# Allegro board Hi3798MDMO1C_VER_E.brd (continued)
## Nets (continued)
NF_CSN0_EMMC_CMD: R212.2 U1.N22 U19.9 U22.W5
NF_DQ0_EMMC_D0: R189.2 U1.R23 U19.29 U22.H3
NF_DQ1_EMMC_D1: R12.2 U1.R22 U19.30 U22.H4
NF_DQ2_EMMC_D2: R29.2 U1.R21 U19.31 U22.H5
NF_DQ3_EMMC_D3: R58.2 U1.T21 U19.32 U22.J2
NF_DQ4_EMMC_D4: R176.2 U1.T20 U19.41 U22.J3
NF_DQ5_EMMC_D5: R177.2 U1.U22 U19.42 U22.J4
NF_DQ6_EMMC_D6: R188.2 U1.U23 U19.43 U22.J5
NF_DQ7_EMMC_D7_BOOT_SEL0: R33.1 R202.2 U1.U21 U19.44 U22.J6
NF_RDY0_EMMC_RST: C115.1 R203.2 U1.M21 U19.7 U22.U5
NF_REN_EMMC_CLK: R68.1 U19.8 U22.W6
NF_WEN_EMMC_DET: R56.2 U1.P21 U19.18
NF_WP: R89.1 R215.2 U19.19
PWR_OFF/ON: R40.1 R41.1 U1.J23
RECOVERY: C38.2 R25.2 S1.2 U1.J22
RF0: C89.1 L1.2 U7.3
RF1: C56.1 L7.2 U2.7 U7.2
RFF0: C88.1 J9.1 L1.1
RFF1: C50.1 J8.1 L7.1
RX+_PHY0: R63.1 U1.D5 U8.3 U8.6
RX-_PHY0: R64.1 U1.C5 U8.4 U8.5
SPDIF_OUT_BOOT_SEL1: R39.1 U1.A20
STANDBY_PWROFF: R5.1 R47.1 R73.1 R88.1 R98.1 U1.AB23
TX+_PHY0: R59.1 U1.B4 U8.1 U8.8
TX-_PHY0: R62.1 U1.A4 U8.2 U8.7
UART0_RXD: J18.2 R136.1 U1.AA22
UART0_TXD: J18.3 R135.2 U1.AA23
USB0_DM: C48.1 D5.1 J12.2 U1.A6
USB0_DP: C42.1 D4.1 J12.3 U1.B6
USB01_1V1: C334.1 C336.1 LB31.2 U1.G11
USB01_3V3: C10.1 C182.1 LB20.2 U1.D7
USB1_DM: J2.4 U1.B7 U2.4 U7.7
USB1_DP: J2.3 U1.C7 U2.2 U7.6
USB3_DM: J28.2 U1.AC18
USB3_DP: J28.3 U1.AB18
USB3_RXN: J28.5 U1.AB20
USB3_RXP: J28.6 U1.AC20
USB3_TXN: C62.2 U1.AA19
USB3_TXP: C70.2 U1.Y19
USB03_VBUS: C60.1 C265.1 C372.1 J12.1 J28.1 LB2.1 U26.5
USB_BOOT: R42.2 U1.H21
VDAC_3V3: C9.1 C85.1 LB14.2 U1.E20 U1.F19 U1.G19
XIN: C364.1 R1.2 U1.W23 X2.1
XOUT: R1.1 R14.1 U1.W22
$4N588: C84.1 R10.1 R52.1 U15.5
$4N589: L4.1 U15.3
$4N593: C30.1 R6.2 R47.2 U15.1
$4N676: C43.1 C71.1 R7.2 R21.1
$4N677: C76.1 R53.1 R70.1 R99.2 U11.6
$4N679: L2.1 U11.3
$4N687: C8.1 R73.2 U11.1
$4N714: C82.1 R13.2 R101.1 R110.1 U13.6
$4N715: C45.1 C72.1 R23.1 R102.2
$4N716: R102.1 R110.2
$4N719: L3.1 U13.3
$4N724: C5.1 R5.2 U13.1
$4N894: R7.1 R70.2
$4N901: R100.1 R105.1 U14.5
$4N903: D2.1 R95.1 U14.1
$4N904: C83.2 R104.1
$4N905: C24.1 C83.1 U14.6
$4N906: R4.2 U14.7
$4N919: C44.1 U14.8
$4N923: C65.1 R95.2
$4N925: C65.2 L5.1 U14.3
$4N944: J1.1 J5.2 J10.1 R81.1
$5N541: Q4.3 R118.2 R144.2
$5N542: C6.2 Q13.1 Q14.1 R118.1
$5N549: Q4.1 R98.2
$6N188: C365.1 R14.2 X2.3
$6N1407: R173.1 U1.E6
$6N2001: R61.2 U1.Y17
$6N2177: R24.1 R85.1 U1.L19
$6N2378: R68.2 U1.N23
$7N1408: C250.2 U1.G17
$7N1639: R82.2 R87.2 U1.D8
$7N1763: R32.2 U1.F20
$7N1940: C34.1 R42.1 S2.1 S2.2
$8N1506: R45.1 U1.W16
$8N1694: R18.2 U1.AC8
$8N1695: R35.2 U1.AB8
$8N1696: R36.2 U1.AA7
$8N1697: R37.2 U1.AB7
$9N2352: C255.2 U1.T19
$11N1183: R46.2 U3.L8
$11N1256: C328.1 R11.2 R15.1
$12N1465: R71.2 U6.L8
$12N1636: C330.1 R16.2 R17.1
$13N604: C123.1 C124.1 U22.K2
$13N727: R57.1 U19.39
$13N772: R80.2 U19.38
$14N447: R220.1 U26.3
$14N448: R106.2 U26.4
$14N684: C70.1 J28.9
$14N685: C62.1 J28.8
$15N955: Q2.1 R31.2
$15N957: Q1.1 R22.2
$16N873: C363.1 R66.1 R90.2 R229.1 U5.5
$16N884: C32.1 U5.7
$16N889: C33.2 U5.6
$16N895: C32.2 U5.8
$16N998: R43.2 R44.1 R48.2
$16N1000: R43.1 U5.11
$16N1002: C351.2 R193.1
$16N1003: C55.1 R27.2 U5.2
$16N1006: C317.1 R19.1 R27.1 R193.2
$16N1021: C55.2 R19.2 R74.2 R146.1 U5.3
$16N1028: C54.2 R28.1 U5.13
$16N1029: C54.1 R20.1 R72.1 R145.1 U5.12
$16N1040: C350.1 R194.2
$16N1041: C316.1 R20.2 R28.2 R194.1
$17N163: C154.1 C297.1 T2.7
$17N165: J25.9 R67.1
$17N170: J25.11 R79.1
$17N171: J25.7 J25.8 R270.2
$17N172: R271.2 T2.15
$17N173: R269.2 T2.10
$17N175: J25.6 T2.9
$17N176: J25.3 T2.11
$17N177: C23.1 R269.1 R270.1 R271.1 R272.1
$17N178: J25.1 T2.16
$17N179: J25.2 T2.14
$17N180: J25.4 J25.5 R272.2
$17N184: C153.1 C307.1 T2.2
$17N255: R59.2 T2.1
$17N256: R62.2 T2.3
$17N257: R63.2 T2.6
$17N258: R64.2 T2.8
$19N506: D19.1 R268.1

Pads without a net: ID1 1; ID2 1; ID3 1; ID4 1; ID5 1; ID6 1; J2 1 6 8 11; J26 14; M20 1; M21 1; T2 4 5 12 13; U1 A8 A9 A11 A12 AA21 B9 B11 B12 C1 C2 C9 C10 C11 C12 D3 E1 E2 E3 F1 F2 F3 G5 G21 J21 K20 K21 L22 L23 Y22; U2 3; U3 J1 J9 L1 L9; U6 J1 J9 L1 L9; U7 4 9 10; U11 5; U13 5; U19 3 4 5 6 10 11 14 15 20 21 22 26 27 28 33 35 40 45 46 47; U22 A4 A6 A9 A11 AA1 AA2 AA7 AA8 AA9 AA10 AA11 AA12 AA13 AA14 AE1 AE14 AG2 AG13 AH4 AH6 AH9 AH11 B2 B13 D1 D14 H1 H2 H6 H7 H8 H9 H10 H11 H12 H13 H14 J1 J7 J8 J9 J10 J11 J12 J13 J14 K1 K3 K5 K7 K8 K9 K10 K11 K12 K13 K14 L1 L2 L3 L4 L12 L13 L14 M1 M2 M3 M5 M8 M9 M10 M12 M13 M14 N1 N2 N3 N10 N12 N13 N14 P1 P2 P3 P10 P12 P13 P14 R1 R2 R3 R5 R12 R13 R14 T1 T2 T3 T5 T12 T13 T14 U1 U2 U3 U6 U7 U10 U12 U13 U14 V1 V2 V3 V12 V13 V14 W1 W2 W3 W7 W8 W9 W10 W11 W12 W13 W14 Y1 Y3 Y6 Y7 Y8 Y9 Y10 Y11 Y12 Y13 Y14

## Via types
v1: diameter 0.508, hole 0.254, TOP to BOTTOM, 1411 vias
v2: diameter 0.457, hole 0.203, TOP to BOTTOM, 873 vias

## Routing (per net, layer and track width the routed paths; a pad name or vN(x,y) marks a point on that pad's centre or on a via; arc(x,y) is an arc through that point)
1V1_CORE: length 8.2
  TOP w0.381: 82.04,31.36 83.57,31.36 84.77,30.16 84.77,26.07 C82.2
  TOP w0.508: R101.2 C82.2
  vias: v1(76.45,33.01) v1(76.43,32.23) v1(76.41,31.53) v1(77.16,32.23) v1(77.13,31.52) v1(77.19,32.99) v1(77.98,32.99) v1(78.71,32.99) v2(65.22,46.63) v2(65.22,45.84) v2(65.22,45.03) v2(66.02,45.84) v2(66.02,45.03) v2(66.82,45.84) v2(67.62,48.25) v2(67.62,45.83) v2(68.42,48.23) v2(68.42,47.43) v2(68.42,45.83) v2(70.66,41.75) v2(70.66,41.17) v2(71.24,41.75) v2(71.24,41.17) v2(71.83,41.75) v2(71.83,41.17)
1V1_CPU: length 12.2
  TOP w0.381: R53.2 C76.2 v1(98.17,57.07)
  BOTTOM w0.381: v1(98.17,57.07) 92.75,57.07 89.37,53.69 v1(89.37,53.34)
  vias: v1(86.43,49.18) v1(87.16,48.8) v1(87.96,49.19) v1(88.63,48.8) v1(89.37,50.61) v1(89.37,49.85) v1(89.37,49.09) v1(90.26,50.61) v1(90.26,49.85) v1(90.26,49.09) v2(70.02,49.03) v2(70.02,46.63) v2(70.82,49.03) v2(70.82,48.23) v2(70.82,47.44) v2(70.82,46.63)
1V5_DDR3: length 35.7
  TOP w0.254: v1(14.17,43.95) 15.79,45.57 15.79,46.73 ; U6.F1 46.61,32.63 v2(46.61,33.15) ; C84.2 7.05,44.73 R10.2 v1(7.04,43.99)
  TOP w0.305: U6.K2 v2(43.01,32.22) ; v2(41.01,49.66) U3.N1 ; U6.G7 v2(45.41,28.22) ; U6.K8 v2(43.81,27.42) ; U6.E9 v2(47.41,25.67) ; v2(50.61,49.58) U3.A1 ; U6.B2 v2(50.22,32.23) U6.A1 v2(50.61,33.17) ; v2(44.91,25.67) 45.01,25.77 U6.H9 ; U3.D2 v2(48.61,47.83) ; U3.G7 45.81,44.76 v2(45.8,44.77) ; v2(49.01,49.58) U3.C1 ; U3.K2 v2(43.01,48.63) ; U3.H2 v2(45.41,48.63) ; v2(39.41,33.25) U6.R1 ; v2(51.21,26.92) 51.11,27.02 U6.A8 ; U3.K8 v2(43.81,43.83) ; U6.N9 v2(41.01,25.67) ; U6.C9 49.01,25.85 v2(49.17,25.69) ; U3.H9 v2(45.01,42.09) ; U6.C1 v2(49.01,33.17) ; U3.E9 v2(47.41,42.09) ; v2(41.01,33.25) U6.N1 ; v2(46.61,49.71) 46.61,49.66 46.61,49.66 U3.F1 ; U3.N9 v2(41.01,42.09) ; U3.R9 v2(39.41,42.09) ; U3.B2 v2(50.22,48.64) ; U6.R9 39.41,25.95 39.2,25.74 v2(39.19,25.74) ; v2(51.37,42.98) 51.37,43.09 51.02,43.43 U3.A8 ; U6.D9 v2(48.21,25.67) ; U6.D2 v2(48.61,31.42) ; U6.H2 v2(45.41,32.22) ; U3.D9 v2(48.21,42.09) ; U3.C9 v2(49.01,42.09) ; v2(39.41,49.66) U3.R1
  BOTTOM w0.254: v2(62.02,47.43) 61.86,47.27 C97.1 ; v1(14.17,43.95) 14.16,43.97 7.06,43.97 v1(7.04,43.99) ; C100.1 62.02,48.83 v2(62.02,48.23)
  BOTTOM w0.381: C137.1 61.93,40.16
  vias: v2(17.03,47.78) v2(17.03,46.9) v2(17.79,47.78) v2(17.79,46.9) v2(60.42,40.23) v2(61.22,41.83) v2(61.22,41.03) v2(61.22,40.23) v2(62.02,42.63) v2(62.02,41.83) v2(62.02,41.03) v2(62.02,40.23) v2(62.17,46.17) v2(62.14,44.91) v2(64.42,42.63) v2(64.42,41.83) v2(66.82,41.83) v2(67.62,41.83)
3V3: length 68.4
  TOP w0.254: R2.1 113.54,18.05 112.73,17.24 v1(112.73,17.03)
  TOP w0.305: U1.W20 U1.V20 73.22,41.83 v2(73.22,41.84)
  TOP w0.381: R6.1 11.5,46.14 v1(11.3,46.34) ; v1(117.63,17.29) 117.84,17.08 R140.2 ; v1(86.4,22.52) 86.78,22.9 86.78,33.45 85.66,34.57 v1(85.24,34.57) R88.2 ; R178.2 118.85,17.07 v1(119.05,17.26) ; 84.99,20.41 85.8,20.41 v1(85.8,20.41) ; 84.99,20.41 R136.2 ; 84.99,20.41 R135.1 83.71,20.41 83.26,19.95 83.26,19.19 82.47,18.41 J18.4 v1(80.53,17.85) ; R105.2 v1(9.77,55.2) ; R3.1 v1(116.56,14.42)
  BOTTOM w0.254: v1(99.09,9.45) 98.18,9.45 R65.1
  BOTTOM w0.381: R34.1 105.68,14.07 106.85,12.9 v1(106.85,12.31) ; v1(85.8,20.41) 85.8,21.92 v1(86.4,22.52) ; 76.56,41.74 77.72,41.74 C13.1 84.02,41.8 85.54,40.28 85.54,34.87 v1(85.24,34.57) ; 76.56,41.74 C108.1 ; 76.56,41.74 73.31,41.74 v2(73.22,41.84) ; v1(11.3,46.34) 11.18,46.47 3.49,46.47 v1(3.48,46.47)
  BOTTOM w0.508: v1(4.21,55.2) v1(9.77,55.2)
  vias: v1(1.94,41.27) v1(2,41.99) v1(2.67,41.23) v1(2.71,41.95) v1(3.45,41.97) v1(3.45,41.25) v1(64.92,10.54) v1(64.93,9.83) v1(64.92,9.11) v1(65.63,10.57) v1(65.64,9.86) v1(65.63,9.14) v1(77.39,22.44) v1(78.17,22.44) v1(78.14,21.53) v1(78.95,22.43) v1(78.97,21.52) v1(79.22,9.69) v1(79.23,8.97) v1(79.75,22.44) v1(80.18,8.98) v1(80.19,9.69) v1(105.36,51.92) v1(105.37,51.14) v1(106.1,51.91) v1(106.1,51.13) v1(106.81,51.9) v1(106.82,51.12) v1(109.35,14.49) v1(109.32,13.73) v1(110.08,14.47) v1(110.08,13.73) v1(110.87,14.44) v1(110.85,13.71) v1(117.65,18.07) v1(118.36,18.07) v1(118.34,17.29) v1(119.08,18.07) v1(119.91,40.68) v1(119.89,39.96) v1(120.72,40.7) v1(120.72,39.96) v1(121.51,40.67) v1(121.51,39.96)
3V3_IR: length 6.9
  BOTTOM w0.305: J3.2 115.75,13.69 v1(119.85,13.69)
3V3_MOS: length 236.8
  TOP w0.254: v1(71.55,84.34) 71.55,83.58 70.26,82.29 R25.1
  TOP w0.305: U1.D12 v2(66.82,52.23)
  TOP w0.381: v1(32.03,68.06) 31.98,68.06 31.82,68.22 D19.2 ; J25.10 39.73,76.74 37.85,76.74 37.37,76.25 37.37,70.13 37.94,69.55 R26.1 v1(38.08,68) ; R30.1 53.8,65.24 54.33,65.78 54.33,67.92 54.33,68.24 54.33,68.24 54.33,68.77 v1(54.33,68.77) 54.33,68.78 54.33,69.38 54.33,69.38 54.33,73.56 52.88,75.02 J25.12
  TOP w0.762: v1(114.8,66.13) 114.81,66.12 114.81,65.5 109.28,59.97
  TOP w1.016: v1(16.31,17.83) 16.31,14.04 20.1,10.25 61.31,10.25 64.6,13.54 66.67,13.54 Q13.3
  BOTTOM w0.381: v1(32.03,68.06) 38.02,68.06 v1(38.08,68) 38.25,67.83 53.39,67.83 v1(54.33,68.77) ; LB35.1 71.58,51.47 v2(71.62,51.43)
  BOTTOM w0.508: 72.37,34.83 72.38,34.84 LB18.1
  BOTTOM w0.762: 114.81,66.96 114.81,66.14 v1(114.8,66.13) ; 114.81,66.96 v1(114.8,66.95) ; 114.81,66.96 114.81,68.62 112.65,70.77 112.65,81.26 109.42,84.5 96.45,84.5 93.6,81.65 91.71,81.65 88.26,85.1 72.31,85.1 v1(71.55,84.34) 71.52,84.31 60.71,84.31 J25.12 ; v1(68.28,14.13) 67.74,14.67 67.74,21.85 72.37,26.47 72.37,34.83
  BOTTOM w1.016: v1(16.31,17.83) 15.46,18.69 v1(15.45,18.69) 15.45,18.69 13.56,20.58 LB4.2
  vias: v1(106.26,61.87) v1(106.24,61.09) v1(106.97,61.88) v1(106.96,61.14) v1(113.26,45.64) v1(113.23,44.88) v1(114,45.63) v1(114,44.86) v1(114.76,44.87) v1(114.78,45.61) v1(116.85,37.74) v1(116.81,36.94) v1(117.57,37.75) v1(117.57,36.94) v1(118.31,37.78) v1(118.29,36.96) v2(61.22,51.44) v2(62.64,50.29) v2(63.23,50.29) v2(64.27,51.41) v2(71.62,50.63) v2(72.42,49.83) v2(72.42,45.83)
3V3_MOS_FLASH: length 52.7
  TOP w0.203: U22.Y4 U22.AA3
  TOP w0.254: U22.AA5 v2(99.16,37.56) ; U22.Y4 U22.W4 v2(99.66,35.5) ; v2(98.3,32) 98.66,31.64 U22.K6 ; v2(98.3,32) 96.49,32 96.13,32.36 96.13,34.13 96.5,34.5 U22.T10 96.66,34.51 v2(97.16,34.51) U22.U9 97.16,35.12 v2(96.76,35.52) ; v2(98.3,32) 98.66,32.36 U22.M6 98.66,33.03 v2(98.62,33.07) 99.09,33.07 U22.N5 ; v1(91.82,42.28) 92.16,42.62 U19.24 ; U19.34 96.66,22.99 v2(96.52,22.85) ; v2(98.41,42.36) 98.16,42.62 U19.12 ; v2(103.89,42.28) 103.66,42.51 U19.1 ; U22.AA3 100.16,37.02 v2(100.7,37.56) ; v2(98.29,25.14) 98.16,25.01 U19.37
  TOP w0.381: R176.1 v1(97.8,20.31) ; v2(100.7,37.56) 100.7,37.74 100.3,38.15 99.41,38.15 99.16,37.9 v2(99.16,37.56) ; R189.1 v1(91.31,20.92) ; R12.1 v1(93.6,20.31) ; R202.1 101.61,20.44 v1(101.48,20.31) ; R58.1 v1(96.39,20.31) ; v1(98.82,20.31) 99.07,20.56 R177.1 ; R29.1 v1(95.12,20.31) ; R188.1 100.34,20.44 v1(100.21,20.31)
  BOTTOM w0.305: v2(98.41,42.36) 98.41,41.6 C143.1 ; C275.1 98.28,31.98
  BOTTOM w0.381: v2(99.66,35.5) 99.85,35.69 C63.1 101.34,35.69 R203.1 ; v2(99.66,35.5) 99.64,35.5 99.03,34.89 99.03,33.66 99.24,33.45 C93.1 98.82,32.87 v2(98.62,33.07) 98.62,32.32 v2(98.3,32) 98.28,31.98 ; v2(99.66,35.5) 99.66,36.42 C324.1 99.16,36.92 v2(99.16,37.56) ; v2(103.89,42.28) 103.89,41.9 104.85,40.94 R91.1 ; C143.1 98.44,41.13 v2(97.84,40.53) ; R212.1 96.87,35.62 v2(96.76,35.52) 96.76,35.52 96.76,35.52 96.51,35.28 C105.1 97,34.67 v2(97.16,34.51) ; v2(100.7,37.56) 100.7,37.79 C323.1 ; v2(98.29,25.14) 98.32,25.1 C142.1 ; v2(94.97,39.49) 94.27,39.49 93.85,39.91 R215.1 92.98,40.48 92.46,41.01 92.46,41.75 91.92,42.28 v1(91.82,42.28)
  BOTTOM w0.508: C275.1 97.49,31.72 96.41,30.64 95.59,30.64
  vias: v1(105.62,40.15) v1(105.61,39.41) v1(106.35,40.16) v1(106.38,39.42) v2(93.14,30.4) v2(93.78,30.41)
3V3_WIFI: length 3.2
  BOTTOM w0.254: LB4.1 11.95,26.52 C15.1 11.9,28.05 C61.1
  vias: v1(10.29,28.98) v1(10.28,28.25) v1(11.02,28.99)
5V0: length 13.1
  TOP w0.254: 18.61,61.49 18.61,59.04 R144.1 ; R4.1 v1(15.19,55.33)
  BOTTOM w0.254: v1(18.82,62.19) 17.69,61.05 17.69,57.92 15.19,55.42 v1(15.19,55.33)
5V0_MOS: length 29.5
  TOP w0.381: v1(84.62,62.09) 84.86,62.34 94.53,62.34 95.02,62.83 100.05,62.83 100.54,62.34 102.66,62.34 102.86,62.54 R179.1
  TOP w0.457: v1(36.91,66.61) 35.57,67.95 D20.2
  BOTTOM w0.381: v1(84.62,62.09) 84.62,69.01
  vias: v1(84.2,69.83) v1(84.18,69.11) v2(19.23,59.4) v2(19.29,60.15) v2(19.95,59.4) v2(19.98,60.13)
5V0_MOS_HDMI: length 17.4
  TOP w0.254: 28.98,75.61 28.47,76.11 J26.18
  TOP w0.508: U4.5 32.9,71.69 D20.1 C150.1 35.57,74 R187.2 35.56,74.72 34.98,75.3 v1(32.11,75.3) 29.29,75.3 28.98,75.61 ; R186.2 v1(32.11,74.03)
  BOTTOM w0.508: v1(32.11,75.3) v1(32.11,74.03)
AVDD11_PLL012: length 0.6
  TOP w0.305: U1.P17 70.42,44.63 70.42,44.63 v2(70.02,45.03)
AVDD11_USB3:
  vias: v2(70.02,43.43)
AVDD33_ADAC: length 0.6
  TOP w0.127: U1.E19 v2(72.42,52.24)
AVDD33_PLL01: length 0.6
  TOP w0.305: v2(72.4,44.24) 72.02,43.86 U1.R19
AVDD33_USB2: length 1.4
  TOP w0.203: v2(72.42,49.03) 72.42,48.24 U1.K19
AVDD33_USB3: length 5.5
  TOP w0.203: U1.W17 70.5,40.71 71.15,40.71 U1.W18
  TOP w0.254: v2(71.62,40.24) 71.39,40.47 U1.W18
  BOTTOM w0.381: LB18.2 72.38,37.69 C18.1 72.38,38.62 71.62,39.38 v2(71.62,40.24)
GND: length 1337.3
  TOP w0.089: v2(101.6,36.76) 100.91,36.76 U22.Y2
  TOP w0.102: U1.R2 55.92,43.83 55.85,43.77 ; v2(59.73,32.27) 59.73,32.27 60.02,32.56 U1.AB4
  TOP w0.127: v2(51.33,44.66) 51.73,44.66 51.75,44.68 53.68,44.68 54.61,45.61 56.44,45.61 56.61,45.78 57.97,45.78 ; 28.7,13.52 28.93,13.29 60.94,13.29 ; v2(40.61,47.84) 40.61,47.05 v2(40.6,47.04) 40.55,47.04 40.35,46.85 37.13,46.85 36.9,47.08 v2(36.46,47.08) ; U1.C17 71.09,54.11 71.09,55.84 71.55,56.3 v2(71.55,56.71) ; 69.25,38.61 69.25,37.97 69.58,37.64 ; 69.25,38.61 69.81,38.61 70.23,39.03 U1.AA17 ; 69.25,38.61 U1.AA15 ; 72.49,38.55 72.47,38.52 72.47,37.23 72.69,37 ; U1.Y9 64.42,39.44 64.42,38.86 64.82,38.46 U1.AB10 64.82,26.49 64.5,26.16 ; v2(66.45,24.33) 66.63,24.51 66.63,37.05 66.76,37.19 66.76,37.69 66.42,38.03 U1.AB12 ; U19.36 97.66,23.85 ; v2(35.11,43.71) 36.21,44.82 39.81,44.82 ; U1.AC11 65.62,37.2 65.74,37.08 65.74,25.48 v2(65.4,25.13) ; 39.81,44.82 40.23,44.82 40.61,44.43 v2(40.61,43.83) 40.61,43.25 40.21,42.85 U3.P9 ; 39.81,44.82 39.81,44.02 39.62,43.83 38.36,43.83 ; v2(66.93,22.98) 67.44,23.48 67.44,37.66 67.59,37.81 67.59,38.61 U1.AA14 ; v2(62.38,26.04) 63.86,27.51 63.86,27.52 64.02,27.68 U1.AC9 ; v2(38.61,40.26) 39.02,40.67 40.41,40.67 ; 47.81,42.29 47.81,41.88 ; 60.11,53.82 60.11,53.83 60.42,54.13 60.42,55.3 59.87,55.85 59.87,55.94 ; U3.E2 47.41,48.23 47.78,47.85 47.78,47.17 48.38,46.57 49.35,46.57 49.35,46.57 49.67,46.57 49.67,46.57 50.9,46.57 51.71,47.38 v2(52.43,47.38) ; v2(43.15,45.24) 43.11,45.28 35.45,45.28 35.17,45 ; v2(58.82,41.03) 58.42,41.03 58.37,40.98 56.98,40.98 55.88,39.87 55.88,33.82 51.41,29.35 49.73,29.35 v2(49.23,28.85) 48.71,28.33 v2(48.7,28.33) 48.61,28.24 48.61,27.7 48.9,27.4 50.04,27.4 50.17,27.53 50.17,28.12 ; v2(43.01,31.42) 42.4,31.42 42.17,31.19 42.17,30.48 41.41,29.72 37.27,29.72 37.07,29.92 ; U1.Y1 57.5,39.83 v2(57.15,39.49) ; U6.P1 40.21,32.31 40.62,31.9 40.62,30.76 40.32,30.45 37.99,30.45 37.72,30.72 ; U1.L3 58.84,47.42 59.22,47.81 U1.K3 ; U1.L3 58.88,46.69 57.46,46.69 57.3,46.85 56.41,46.85 ; U1.L3 U1.L4 ; v2(72.42,39.43) 72.45,39.41 ; v2(60.12,28.97) 61.85,30.7 61.85,37.1 61.98,37.23 61.98,37.63 61.62,37.99 U1.AB6 ; U1.AA8 62.85,38.67 62.85,36.89 62.66,36.7 62.66,34.99 62.84,34.81 ; 35.26,29.01 35.85,28.42 40.16,28.42 40.62,27.97 40.62,26.8 40.21,26.39 U6.P9 ; v2(45.04,45.87) 45.04,44.78 44.63,44.37 44.63,43.86 U3.J8 ; v2(54.81,38.34) 54.81,40.46 56.23,41.87 57.86,41.87 58.22,42.23 U1.U2 ; 41.61,28.75 41.49,28.88 36.51,28.88 v1(35.97,29.41) ; U1.N2 58.31,45.43 ; 34.22,45.81 34.33,45.92 34.34,45.92 34.48,46.06 41.4,46.06 41.48,46.15
  TOP w0.152: v2(48.61,43.83) 49.94,43.83 50.2,44.09 50.2,44.53 50.35,44.68 50.9,44.68 50.92,44.66 v2(51.33,44.66) ; U3.T1 38.61,48.77 39.02,48.36 39.02,48.11 39.3,47.83 40.6,47.83 v2(40.61,47.84) 40.62,47.85 40.62,48.41 40.21,48.82 U3.P1 ; v2(47.06,44.8) 47.02,44.76 47.02,44.02 47.25,43.79 47.25,43.59 U3.E8 ; 69.47,55.95 69.47,54.08 v2(69.22,53.83)
  TOP w0.165: U1.Y7 62.03,39.45 62.03,38.84 61.62,38.42 U1.AB6
  TOP w0.203: 32.06,17.78 32.62,17.22 57.49,17.22 v1(58.03,17.77) ; U1.AB4 60.02,38.42 60.43,38.84 60.43,39.22 60.23,39.42 59.61,39.42 U1.AA3 ; 53.8,39.34 v2(53.73,39.28) 53.73,40.49 56.27,43.03 U1.T1 ; RN5.7 28.38,36.83 28.7,37.15 ; 30.4,15.53 30.71,15.22 59.19,15.22 59.45,15.48 59.62,15.65 ; U1.AC3 59.22,33.53 v2(51.37,25.67) ; U6.M9 41.74,26.15 41.74,25.16 41.76,25.14 ; v2(68.42,36.68) v2(68.42,38.64) ; 33.48,18.19 56.52,18.19 57,18.66 ; 29.55,14.53 29.82,14.26 60.03,14.26 60.24,14.46 ; U3.J8 43.82,43.04 43.82,41.74 43.69,41.62 v2(43.69,40.82) ; v1(58.71,16.59) 58.31,16.19 31.65,16.19 31.33,16.5 ; v2(44.62,32.23) 44.62,32.44 44.61,32.45 44.62,32.46 44.62,32.79 44.61,32.8 44.62,32.81 44.62,32.96 44.28,33.3 44.28,35.33 41.92,37.69 40.9,37.69 33.71,30.51 v2(33.71,29.95) ; U22.Y5 U22.AA6
  TOP w0.229: v2(99.16,32) 99.66,31.5 U22.K4
  TOP w0.254: v2(38.23,49.48) 38.61,49.1 U3.T1 ; 97.66,23.85 97.66,22.97 v1(97.16,22.47) ; J26.5 21.97,76.17 v1(22.02,76.13) ; v2(69.16,73.45) 68.9,73.71 C48.2 ; 75.75,51.59 75.52,51.36 74.9,51.36 U1.E22 ; 79.76,46.82 v1(81.11,46.82) ; v2(67.42,54.58) 67.22,54.39 U1.C13 ; C42.2 68.61,71.26 v2(69.22,71.26) ; v2(36.46,48.31) 37.07,48.31 37.52,47.85 v2(37.73,47.85) ; v2(48.72,34.19) 48.21,33.68 U6.D1 U6.E1 ; U19.2 103.16,42.32 v2(103.12,42.28) ; S2.5 112.01,58.53 v1(112.01,58.98) ; v1(69.42,21.76) 69.58,21.92 v2(69.58,27.42) 69.58,27.88 69.59,27.89 v2(69.59,31.72) v2(69.59,33.5) v2(69.59,36.68) 69.59,37.63 69.58,37.64 ; U19.13 97.66,42.37 v2(97.66,42.36) ; U1.M20 U1.L20 U1.L21 ; v2(49.81,49.8) 50.04,50.04 51.24,50.04 v2(51.62,49.66) ; 27.67,36.83 RN5.2 26.58,36.83 ; 27.67,36.83 27.66,36.82 ; 27.67,36.83 RN5.7 ; v2(92.71,42.28) 92.66,42.33 U19.23 ; U1.C22 74.64,53.21 75.7,53.21 76.12,53.63 ; v1(91.47,22.85) 91.82,22.85 92.16,23.19 U19.25 ; U1.Y7 U1.AA8 ; v2(97.53,25.14) 97.66,25.01 U19.36 ; v1(34.06,72.35) 34.49,72.35 34.75,72.61 C150.2 ; v2(98.29,37.56) 98.66,37.19 U22.AA6 ; v2(59.62,48.23) U1.K3 ; v1(116.33,18.15) 116.2,18.02 R77.2 ; U1.AA3 v2(58.82,38.64) ; 97.99,67.34 v1(97.99,67.31) 98.42,67.74 U5.10 ; v2(99.94,37.56) 99.66,37.28 U22.AA4 ; U19.48 103.66,25.16 v2(103.76,25.26) ; 99.16,36.55 U22.Y5 ; 79.72,47.73 81.03,47.73 ; U1.AA17 v2(70.82,39.43) ; v2(57.22,37.84) U1.AB1 57.62,38.23 v2(58.02,37.83) U1.AC1 v2(57.22,37.03) ; U1.AA2 v2(58.02,38.64) ; 38.36,43.83 v2(37.93,43.83)
  TOP w0.305: U3.A9 v2(50.61,41.88) ; U1.B20 v2(73.22,54.64) ; U6.B1 v2(49.81,33.17) ; U1.G16 69.62,50.23 U1.H15 v2(69.22,49.04) U1.J15 ; v2(73.22,53.03) 73.62,53.43 U1.C21 73.62,53.64 v2(73.94,53.96) 74.42,53.48 U1.C22 U1.D22 v2(74.82,52.24) U1.E22 U1.E21 U1.D21 73.62,52.63 v2(73.22,53.03) ; v2(73.22,53.03) U1.D20 ; v2(73.22,53.03) U1.C20 U1.D19 ; v2(63.15,46.76) 63.22,46.69 U1.M8 ; U1.N17 70.42,45.44 v2(70.82,45.84) ; U1.H13 v2(66.82,49.83) U1.G12 ; U3.G8 U3.G9 ; U1.E17 70.42,51.83 v2(70.02,52.23) 69.62,51.84 U1.E16 ; v2(66.82,41.03) U1.W13 v2(67.62,41.03) ; v2(69.22,53.83) 68.82,53.44 U1.C15 U1.D15 ; v2(59.62,45.84) 59.22,45.44 U1.N3 U1.N2 ; U1.Y20 v2(72.42,39.43) ; U1.H12 v2(66.82,49.04) ; U1.F21 73.14,50.56 U1.G20 v2(73.22,49.84) 72.82,49.44 U1.H20 ; U1.Y7 62.42,39.84 v2(62.82,40.24) 63.22,40.63 U1.W8 ; v2(52.43,47.38) 52.88,47.83 U1.K1 ; v2(45.81,25.67) U6.G9 U6.G8 ; U3.E8 v2(47.81,43.83) ; U3.B3 v2(50.22,47.84) ; U1.C8 63.22,53.43 v2(63.62,53.84) U1.B8 ; v2(66.02,46.64) 66.42,47.03 U1.L12 ; v2(66.02,46.64) U1.M11 ; v2(66.02,46.64) U1.M12 ; v2(66.02,46.64) U1.L11 ; U1.B3 U1.C3 U1.C4 U1.D4 59.82,52.44 59.82,52.03 U1.E4 U1.F4 60.02,51.03 v2(59.62,50.63) U1.G3 ; v2(45.7,49.76) 45.7,49.14 U3.G1 ; v2(59.62,41.83) U1.V4 v2(60.42,41.83) ; U1.Y3 U1.W3 v2(58.82,41.03) ; U1.D14 68.02,52.63 v2(67.62,52.23) U1.D13 U1.C13 ; 66.02,48.24 U1.J11 ; v2(68.42,38.64) U1.AA15 68.82,39.03 v2(68.42,39.43) U1.AA14 ; U1.C6 v2(62.02,53.04) U1.D6 ; U3.P9 40.21,42.09 ; U1.C17 v2(70.82,53.03) U1.D17 ; U3.F9 v2(46.61,42.09) ; U1.K12 66.42,47.83 v2(66.02,47.44) U1.K11 ; U24.8 U24.3 ; v2(44.62,32.23) U6.J2 ; U3.B9 v2(49.81,41.88) ; U3.E2 U3.E1 U3.D1 v2(48.21,49.61) ; U3.B1 v2(49.81,49.8) ; U6.T9 v2(37.92,26.22) ; v2(59.62,44.23) U1.R4 ; U1.A23 v2(75.62,54.64) U1.B23 ; U6.B9 50.36,25.67 v2(50.61,25.67) U6.A9 ; v2(46.81,24.92) 46.61,25.12 U6.F9 ; v2(66.82,42.63) 66.73,42.54 66.11,42.54 U1.T11 ; U1.AA13 v2(66.82,39.43) ; v2(64.42,41.03) U1.V10 64.82,41.44 ; U6.T1 38.61,33.22 38.62,33.23 v2(38.62,33.25) ; U6.P9 40.21,25.72 v2(40.18,25.69) ; U1.P19 v2(72.42,45.03) 72.82,44.63 U1.P20 ; v2(45.81,33.53) U6.G1 ; v1(70.23,21.22) 70.39,21.38 70.39,38.55 70.42,38.58 U1.AA17 ; U23.8 U23.3 ; U1.H14 68.02,49.44 v2(67.62,49.83) U1.G13 ; U1.D9 v2(63.62,52.23) ; U1.AA18 v2(70.82,39.43) U1.Y18 ; v2(40.82,24.21) 41.76,25.14 ; U6.E2 U6.E1 ; U6.M1 v2(41.81,33.25) ; v2(41.81,49.66) U3.M1 ; U3.D8 v2(48.61,43.83) ; U1.P16 v2(70.02,44.24) ; U1.K5 v2(60.42,48.23)
  TOP w0.381: 76.09,76.91 J28.10 ; J28.10 77.12,75.22 ; J28.10 78.15,76.91 ; 75.31,74.12 J28.4 ; J28.4 75.31,76.05 ; J28.4 76.27,75.08 ; J28.4 74.34,75.08 ; 111.81,68.16 D9.1 ; D9.1 111.02,69.08 ; D9.1 112.6,69.08 ; D9.1 111.81,69.99 ; 10.36,82.51 10.36,82.51 J1.3 ; J3.4 118.8,11.72 ; J3.4 117.79,10.4 ; J3.4 117.79,13.05 ; J3.4 116.77,11.72 ; 17.22,82.73 J26.23 ; J26.23 18.42,84.55 ; J26.23 16.03,84.55 ; J34.7 105.18,80.83 ; J34.7 100.5,80.83 ; J34.7 102.84,79.16 ; 117.84,79.16 J34.8 ; J34.8 117.84,82.51 ; J34.8 115.5,80.83 ; J34.8 120.18,80.83 ; v2(43.31,34.34) 43.31,34.75 42.02,36.04 ; J1.3 7.66,80.97 7.66,80.97 ; J1.3 9.82,81.24 ; 77.12,64.88 J28.13 ; J28.13 77.12,67.54 ; J28.13 78.15,66.21 ; C79.2 107.87,72.53 ; 16.61,9.22 J2.12 15.55,10.67 ; U6.B3 v2(50.22,31.43) ; 17.22,76.51 J26.21 ; J26.21 18.42,78.59 ; J26.21 17.22,80.68 ; J26.21 16.03,78.59 ; J28.7 74.47,71.58 ; J28.7 73.51,70.62 ; J28.7 72.54,71.58 ; J28.7 73.51,72.55 ; 101.7,71.14 102.23,71.14 ; J26.22 32.92,84.55 ; J26.22 31.72,82.73 ; J26.22 30.53,84.55 ; 3.2,9.22 J2.7 4.26,10.67 ; 12.55,10.67 J2.10 11.48,9.22 ; 39.71,50.85 40.21,50.35 U3.P1 ; 118.98,10.57 D3.2 117.91,9.5 ; 8.33,9.22 J2.9 7.26,10.67 ; J1.2 4.18,79.01 ; J1.2 2.86,81.17 ; J1.2 1.54,79.01 ; J1.2 2.86,76.85 ; U1.A2 v2(58.02,55.44) U1.A1 ; J34.6 90.18,80.83 ; J34.6 85.5,80.83 ; J34.6 87.84,79.16 ; J34.6 87.84,82.51 ; 4.96,83.92 J10.3 3.62,81.99 ; 71.7,75.58 J28.11 ; J28.11 70.67,76.91 ; J28.11 71.7,78.24 ; J28.11 72.73,76.91 ; 106.98,72.43 R9.2 106.45,71.9 ; 110.54,70.55 C17.2 111.07,71.08 ; v1(41.43,51.36) 41.81,50.98 v2(41.81,49.66) ; 95.12,61.81 R50.2 ; 5.73,84.19 J10.2 9.59,84.19 ; J26.20 31.72,80.68 ; J26.20 32.92,78.59 ; J26.20 30.53,78.59 ; J26.20 31.72,76.51 ; 12.87,34.2 J2.2 12.87,38.24 ; v2(51.37,25.67) v2(50.61,25.67)
  TOP w0.457: v2(51.47,40.94) 50.93,40.41 47.07,40.41 v2(46.37,41.11) ; v1(62.6,22.34) v2(64.12,23.85) v2(65.4,25.13) ; v2(37.68,35.96) 38.55,36.83 v2(38.56,36.83) v2(39.43,37.69) v2(40.29,38.56) ; 58.15,48.91 U1.J2 ; v1(93.1,46.82) 96.54,46.82 96.55,46.83 v1(97.16,46.83) 99.21,46.83 v1(99.31,46.73) v1(100.2,45.84) ; v2(53.73,39.28) 51.6,37.15 51.58,37.15 v1(51.23,36.8) 50.88,36.45 50.88,36.43 48.72,34.27 v2(48.72,34.19) ; v2(60.12,28.97) v2(58.31,27.16) v2(56.66,25.51) v2(55.12,23.98) 54.13,22.98 54.13,22.98 v1(53.7,22.55) ; v2(54.81,38.34) v1(53.33,36.86) 51.93,35.46 51.93,35.46 v1(51.5,35.03) 51.12,34.65 51.12,34.65 49.81,33.34 v2(49.81,33.17) ; v1(65.36,19.58) 67.84,22.06 67.84,22.06 68.45,22.67 v1(68.45,24.48) 68.43,24.5 68.43,25.19 68.42,25.2 v2(68.42,26.41) v2(68.42,28.55) v2(68.42,30.45) v2(68.42,33.48) v2(68.42,36.68) ; 83.59,45.94 v1(83.59,45.94) ; 83.59,45.94 v1(87.26,45.94) v1(91.32,45.94) v1(94.88,45.94) v1(97.8,45.94) 98.71,45.94 v1(99.44,45.2) ; 83.59,45.94 v1(80.57,45.94) ; U1.G3 59.05,50.41 54.22,50.41 53.65,50.98 53.65,50.98 v1(53.24,51.39) 52.82,51.81 52.82,51.81 52.41,52.22 v1(49.94,52.22) v1(48.42,52.22) 47.91,52.22 v1(47.43,51.74) 45.7,50.01 v2(45.7,49.76) ; v2(76.84,58.65) v2(76.84,55.85) v2(76.84,54.58) 76.84,54.36 76.12,53.63 ; v2(31.34,54.43) 33.83,54.43 v2(33.83,54.43) 35.95,54.43 v2(35.96,54.43) v2(38.3,54.43) v2(40.5,54.43) 41.71,54.43 v2(42.34,53.8) v2(43.71,52.44) ; v2(59.15,29.78) v2(57.04,27.67) v2(54.96,25.59) v2(53.11,23.74) 52.48,23.11 v2(51.19,23.11) v2(48.72,23.11) 47.58,23.11 v1(46.84,23.85) ; v1(64.38,20.44) 64.81,20.87 64.82,20.87 v1(65.84,21.89) 66.51,22.56 66.52,22.56 v2(66.93,22.98) ; v2(35.71,42.58) 36.86,43.74 v2(36.91,43.74) 37,43.83 v2(37.93,43.83) ; v2(52.43,47.38) 52.12,47.69 52.12,48.05 51.67,48.5 51.67,49.61 v2(51.62,49.66) ; v1(77.86,58.65) v2(77.86,55.85) v2(77.86,54.58) 77.86,53.7 75.75,51.59 ; v2(60.64,24.3) v2(62.38,26.04) ; v1(66.17,18.52) 66.18,18.52 ; v2(36.84,40.26) 36.84,40.23 v2(36,39.4) 36,39.38 v2(35.14,38.52) ; v1(62.79,29.35) 61.4,27.96 v2(61.4,27.15) v2(59.72,25.48) ; 81.03,47.73 v1(87.26,47.73) v1(91.32,47.73) v1(94.88,47.73) 99.71,47.73 v1(100.58,46.85) 101.19,46.25 v1(101.19,45.22) ; v2(64.99,22.87) v1(63.47,21.35) ; v2(48.21,49.61) 48.21,50.13 49.13,51.05 51.74,51.05 ; v2(63.29,24.95) v2(61.64,23.3) ; v1(41.31,53.49) 40.72,53.49 40.72,53.5 v2(39.37,53.5) v2(37.03,53.5) 37.03,53.49 v2(34.9,53.49) 34.89,53.5 v2(32.41,53.5) ; v2(35.11,43.71) v2(34.07,42.67) v2(33.08,41.68) v2(31.91,40.51) v2(30.8,39.41) v2(29.9,38.51) v2(29.06,37.67) ; v1(85.6,46.82) v1(81.11,46.82) ; 44.94,40.82 v2(43.69,40.82) ; v1(89.27,46.82) 89.27,46.82 89.26,46.82 v1(89.27,46.82)
  TOP w0.508: v1(41.31,53.49) v1(42.25,52.55) 43.19,51.61 ; v2(31.27,27.18) v2(31.27,29.03) v2(31.27,30.68) ; v2(30.18,31.83) v2(31.05,32.69) v2(31.92,33.57) v2(32.53,34.18) v2(33.39,35.04) v2(34.26,35.9) v2(35.12,36.77) v2(36,37.64) v2(36.89,38.53) v2(37.75,39.4) v2(38.61,40.26) ; v2(29.32,36.19) v2(30.78,37.65) v2(31.63,38.51) v2(32.49,39.37) v2(33.37,40.25) v2(34.44,41.31) v2(35.71,42.58) ; 59.62,15.65 61.02,17.05 v1(61.02,17.07) v1(62.6,18.66) 63.93,19.98 63.93,19.99 v1(64.38,20.44) ; v2(60.64,24.3) v2(58.86,22.52) v1(57.53,21.19) v1(56.26,19.92) 55.65,19.3 v1(53.22,19.3) v1(50.68,19.3) v1(47.76,19.3) v1(44.84,19.3) v1(41.92,19.3) v1(39,19.3) v1(36.2,19.3) ; v2(33.71,29.95) v2(33.71,26.64) v2(33.71,25.26) v2(33.71,24.02) 33.71,23.32 v2(34.33,22.69) 35.19,21.84 v1(37.09,21.84) v1(39,21.84) v1(41.92,21.84) v1(44.84,21.84) v1(47.76,21.84) v1(50.68,21.84) 52.99,21.84 53.25,22.1 53.25,22.1 v1(53.7,22.55) ; v1(114.22,18.13) 114.27,18.08 114.27,16.96 Q1.2 ; v2(32.56,50.87) 32.58,50.85 v1(34.91,50.85) v1(36.46,50.85) 39.71,50.85 ; v2(37.68,35.96) v2(36.82,35.1) v2(35.94,34.22) v2(32.49,30.77) v2(32.49,29.59) v2(32.49,27.74) v2(32.49,25.98) v2(32.49,24.1) 32.49,22.78 v2(32.55,22.72) v1(33.88,21.4) 34.7,20.57 v1(36.2,20.57) v1(39,20.57) v1(41.92,20.57) v1(44.84,20.57) v1(47.76,20.57) v1(50.68,20.57) 54.82,20.57 v1(55.37,21.12) v1(56.47,22.22) v2(57.96,23.71) v2(59.72,25.48) ; v1(65.36,19.58) v1(63.46,17.68) v1(61.93,16.15) 60.24,14.46 ; v1(32.92,20.57) v2(32.06,21.44) ; v1(63.47,21.35) v1(61.75,19.63) v1(60.23,18.11) v1(58.71,16.59) ; v2(28.53,41.86) v2(29.72,43.05) v2(30.71,44.04) v2(31.73,45.06) v2(32.75,46.08) v2(33.75,47.08) v2(35.36,47.08) v2(36.46,47.08) ; v2(29.61,44.69) v2(30.83,45.91) v2(31.85,46.93) v2(32.89,47.97) 33.23,48.31 v2(34.02,48.31) v2(35.26,48.31) v2(36.46,48.31) ; v2(28.02,38.68) 28.86,38.68 v2(29.34,39.17) v2(30.52,40.35) v2(31.52,41.34) v2(32.48,42.3) v2(33.41,43.23) v2(34.5,44.32) 35.17,45 ; v1(58.03,17.77) v1(59.49,19.23) v1(60.83,20.56) v1(62.6,22.34) ; v2(61.64,23.3) v1(59.86,21.53) v1(58.4,20.07) 57,18.66 ; v2(29.7,41.27) v2(30.66,42.24) v2(31.58,43.15) v2(32.57,44.14) v2(33.62,45.2) ; v2(45.81,33.53) 45.9,33.62 45.9,37.29 45.37,37.82 v2(44.61,37.82) 43.64,37.82 42.73,38.73 40.47,38.73 v2(40.29,38.56) ; v2(38.23,49.48) 38.13,49.58 v2(36.46,49.58) v2(34.17,49.58) 32.75,49.58 v2(32.64,49.48) ; v2(35.14,38.52) v2(34.27,37.65) v2(33.39,36.77) v2(32.51,35.89) v2(31.68,35.06) v2(31.08,34.46) v2(30.19,33.57) v2(29.33,32.71) 28.27,31.65 v2(27.29,31.65) 27.26,31.67 ; v2(29.32,34.44) v2(30.2,35.31) v2(30.81,35.92) v2(31.65,36.76) v2(32.54,37.65) v2(33.39,38.5) v2(34.26,39.38) v2(35.14,40.25) v2(36,41.12) v2(36.9,42.02) ; 64.5,26.16 v2(63.29,24.95)
  BOTTOM w0.127: 69.77,46.16 70.49,46.16 v2(70.82,45.84) ; RN7.7 RN7.2 ; C228.2 42.45,30.53 43.01,31.09 v2(43.01,31.42) ; 69.65,49.26 69.86,49.47
  BOTTOM w0.203: 26.58,36.83 RN5.2 27.63,36.83 ; 27.63,36.83 RN5.7 28.71,36.83 ; 27.63,36.83 27.61,36.85
  BOTTOM w0.254: v2(60.42,50.63) 60.42,50.63 v2(59.62,50.63)
  BOTTOM w0.305: C12.2 72.34,44.95 v2(72.42,45.03)
  BOTTOM w0.381: LED1.2 112.43,9.5 ; LED1.2 111.23,8.31 ; LED1.2 111.23,10.7 ; LED1.2 110.04,9.5 ; J34.7 102.84,82.51 ; J34.7 105.18,80.83 ; J34.7 102.84,79.16 ; J34.7 100.5,80.83 ; J26.22 31.72,86.38 ; J26.22 31.72,82.73 ; J26.22 30.53,84.55 ; J26.22 32.92,84.55 ; J26.23 17.22,86.38 ; J26.23 17.22,82.73 ; J26.23 16.03,84.55 ; J26.23 18.42,84.55 ; 61.25,71.62 J12.4 ; J12.4 62.57,70.55 ; J12.4 63.89,71.62 ; 77.12,75.22 J28.10 ; J28.10 77.12,78.6 ; J28.10 78.15,76.91 ; J28.10 76.09,76.91 ; 73.51,70.62 J28.7 ; J28.7 74.47,71.58 ; J28.7 72.54,71.58 ; J28.7 73.51,72.55 ; v2(74.82,52.24) 74.73,52.15 R32.1 ; J12.6 65.29,72.8 ; J12.6 65.29,69.9 ; J12.6 63.84,71.35 ; 117.84,79.16 J34.8 ; J34.8 115.5,80.83 ; J34.8 120.18,80.83 ; J34.8 117.84,82.51 ; 11.48,9.22 J2.10 12.55,10.67 ; J28.4 76.27,75.08 ; J28.4 74.34,75.08 ; J28.4 75.31,74.12 ; J28.4 75.31,76.05 ; D3.2 118.98,10.57 ; D3.2 120.05,9.5 ; D3.2 118.98,8.44 ; D3.2 117.91,9.5 ; 77.12,64.88 J28.13 ; J28.13 78.15,66.21 ; J28.13 76.09,66.21 ; 9.82,82.51 J1.3 7.66,81.24 ; J12.5 66.73,78.35 ; J12.5 65.29,76.9 ; J12.5 63.84,78.35 ; J12.5 65.29,79.8 ; 30.53,78.59 J26.20 ; J26.20 32.92,78.59 ; J26.20 31.72,76.51 ; J26.20 31.72,80.68 ; J34.6 90.18,80.83 ; J34.6 87.84,79.16 ; J34.6 87.84,82.51 ; J34.6 85.5,80.83 ; 86.22,16.85 J18.1 87.03,17.85 ; 12.87,34.2 J2.2 12.87,38.24 ; 8.33,9.22 J2.9 7.26,10.67 ; J28.11 71.7,78.24 ; J28.11 72.73,76.91 ; J28.11 70.67,76.91 ; J28.11 71.7,75.58 ; 4.26,10.67 J2.7 3.2,9.22 ; 117.79,10.4 J3.4 ; J3.4 118.8,11.72 ; J3.4 116.77,11.72 ; J3.4 117.79,13.05 ; 5.73,84.19 J10.2 9.59,84.19 ; 2.86,76.85 J1.2 ; J1.2 4.18,79.01 ; J1.2 1.54,79.01 ; J1.2 2.86,81.17 ; 70.67,66.21 J28.12 ; J28.12 71.7,67.9 ; J28.12 71.7,64.52 ; J28.12 72.73,66.21 ; J26.21 17.22,80.68 ; J26.21 17.22,76.51 ; J26.21 18.42,78.59 ; J26.21 16.03,78.59 ; 59.85,76.9 J12.7 ; J12.7 61.29,78.35 ; J12.7 59.85,79.8 ; C324.2 98.42,37.44 v2(98.29,37.56) ; 4.96,80.06 J10.3 ; J10.3 3.62,81.99 ; J10.3 4.96,83.92 ; J12.8 59.85,72.8 ; J12.8 61.29,71.35 ; J12.8 59.85,69.9 ; 16.61,9.22 J2.12 15.55,10.67
  vias: v1(0.84,59.87) v1(0.81,57.73) v1(0.81,55.51) v1(0.8,52.4) v1(0.79,49.2) v1(0.8,46.12) v1(0.79,43.7) v1(0.81,40.99) v1(0.79,37.85) v1(0.79,35.89) v1(0.81,33.66) v1(0.81,31.08) v1(0.8,28.39) v1(0.86,21.48) v1(0.89,84.92) v1(0.89,82.38) v1(0.89,79.84) v1(0.89,77.3) v1(0.92,74.74) v1(0.89,72.22) v1(0.89,69.68) v1(0.89,67.14) v1(0.89,64.6) v1(0.92,62.04) v1(0.89,24.6) v1(0.91,18.51) v1(1.04,9.08) v1(2.19,85.86) v1(2.43,83.89) v1(2.43,81.79) v1(2.54,76.03) v1(2.54,73.49) v1(2.54,70.95) v1(2.54,68.41) v1(2.57,65.85) v1(2.57,63.31) v1(2.49,7.97) v1(2.7,61.03) v1(2.92,20.23) v1(3.11,24.02) v1(3.68,14.93) v1(3.68,13.2) v1(4.07,74.51) v1(4.07,71.97) v1(4.07,69.43) v1(4.07,66.89) v1(4.16,84.67) v1(4.1,64.33) v1(4.1,62.42) v1(4.45,47.36) v1(4.42,45.82) v1(4.45,43.26) v1(4.45,40.72) v1(4.47,38.38) v1(4.52,32.57) v1(4.49,28.22) v1(5.08,20.82) v1(5.26,16.75) v1(5.21,13.88) v1(5.32,34.1) v1(5.46,42.03) v1(5.46,39.49) v1(5.38,15.15) v1(5.49,12.49) v1(5.97,44.57) v1(5.97,10.89) v1(6.08,68.82) v1(6.22,40.76) v1(6.35,43.3) v1(6.32,20.82) v1(6.58,15.15) v1(6.6,16.75) v1(6.73,12.49) v1(6.86,47.49) v1(6.82,25.92) v1(6.99,48.88) v1(7.31,42.01) v1(7.37,39.49) v1(7.49,13.83) v1(7.75,57.39) v1(7.75,56.12) v1(7.87,19.07) v1(8,68.81) v1(8.04,48.88) v1(8.1,10.94) v1(8.25,58.92) v1(8.23,17.24) v1(8.38,43.42) v1(8.33,13.02) v1(8.38,7.89) v1(8.43,34.17) v1(8.56,51.55) v1(8.51,40.76) v1(8.63,47.12) v1(8.69,53.28) v1(8.71,15.86) v1(8.71,14.26) v1(8.89,56.63) v1(8.89,45.58) v1(9.1,26.23) v1(9.12,23.73) v1(9.14,11.7) v1(9.25,49.91) v1(9.21,48.99) v1(9.25,47.91) v1(9.27,39.49) v1(9.74,68.8) v1(9.74,44.52) v1(9.7,12.74) v1(9.84,52.12) v1(9.85,42.01) v1(9.88,54.05) v1(10.03,62.98) v1(10.03,61.33) v1(10.03,59.81) v1(10.03,58.03) v1(10.03,47.12) v1(10.01,16.7) v1(10.03,15.41) v1(10.06,14.16) v1(10.21,84.26) v1(10.33,33) v1(10.54,38.6) v1(10.51,25.28) v1(10.79,62.22) v1(10.86,22.92) v1(10.92,45.58) v1(10.92,43.42) v1(10.92,40.76) v1(10.97,7.91) v1(11.07,85.16) v1(11.02,54.03) v1(11.21,33.79) v1(11.42,47.12) v1(11.77,44.52) v1(11.74,21.15) v1(11.81,49.27) v1(11.96,61.49) v1(11.94,38.98) v1(12.04,62.88) v1(12.14,68.74) v1(12.15,32.44) v1(12.19,42.03) v1(12.32,85.21) v1(12.33,74.64) v1(12.41,23.56) v1(12.57,40.76) v1(12.71,57.51) v1(13.11,62.9) v1(13.12,61.45) v1(13.24,19.31) v1(13.34,43.42) v1(13.36,13.73) v1(13.45,33.79) v1(13.57,85.2) v1(13.72,39.74) v1(13.97,54.71) v1(14.15,45.95) v1(14.1,42.15) v1(14.32,62.91) v1(14.33,61.43) v1(14.73,84.95) v1(14.74,32.7) v1(14.76,23.6) v1(14.7,21.06) v1(14.94,30.08) v1(14.89,7.88) v1(14.99,41.01) v1(15.11,45.96) v1(15.28,38.45) v1(15.23,17.28) v1(15.32,43.63) v1(15.44,11.67) v1(15.7,22.09) v1(15.84,85.26) v1(15.88,65.39) v1(15.88,64.35) v1(15.88,63.36) v1(15.88,42.03) v1(15.97,34.27) v1(16,60.95) v1(16,59.17) v1(16.06,54.55) v1(16.13,74.67) v1(16.14,73.63) v1(16.15,30.34) v1(16.33,25.39) v1(16.31,19.77) v1(16.38,45.96) v1(16.51,66.66) v1(17.41,81.76) v1(17.41,74.64) v1(17.43,38.46) v1(17.44,35.62) v1(17.48,33.1) v1(17.48,30.56) v1(17.48,28.02) v1(17.45,25.45) v1(17.44,23.38) v1(17.47,15.44) v1(17.65,45.93) v1(17.77,43.08) v1(17.78,40.63) v1(17.81,56.89) v1(18.16,9.16) v1(18.28,17.64) v1(18.42,54.18) v1(18.58,57.67) v1(18.66,85.54) v1(18.68,83.03) v1(18.68,80.44) v1(18.68,75.91) v1(18.68,73.63) v1(18.74,44.72) v1(18.75,41.97) v1(18.75,39.06) v1(18.74,36.44) v1(18.72,33.17) v1(18.75,31.65) v1(18.75,29.5) v1(18.75,25.8) v1(19.07,78.53) v1(19.01,51.7) v1(19.02,47.2) v1(19.17,56.03) v1(19.27,21.27) v1(19.22,19.04) v1(19.44,74.64) v1(19.43,17.26) v1(19.54,44.17) v1(19.68,52.24) v1(19.84,45.82) v1(19.95,84.3) v1(19.95,81.76) v1(20.01,40.61) v1(20.04,37.04) v1(20.02,35.3) v1(20,34.09) v1(20.01,31.94) v1(20.01,30.5) v1(20.01,28.35) v1(20,25.86) v1(20.21,22.01) v1(20.34,48.38) v1(20.62,65.93) v1(20.76,17.62) v1(20.95,43.77) v1(20.97,23.12) v1(21.11,19.43) v1(21.22,85.57) v1(21.22,83.03) v1(21.2,47.18) v1(21.28,45.91) v1(21.27,34.3) v1(21.27,32.15) v1(21.27,29.41) v1(21.27,27.26) v1(21.28,40.76) v1(21.29,38.51) v1(21.29,36.36) v1(21.44,71.92) v1(21.55,24.4) v1(21.97,42.66) v1(21.95,20.27) v1(22.26,48.23) v1(22.35,56.38) v1(22.35,50.64) v1(22.49,84.3) v1(22.49,81.76) v1(22.57,37.48) v1(22.57,35.33) v1(22.55,32.75) v1(22.57,30.61) v1(22.57,28.46) v1(22.77,45.59) v1(22.87,47.5) v1(22.87,25) v1(22.99,71.97) v1(23.07,42.9) v1(23,17.68) v1(23.18,79.7) v1(23.13,20.94) v1(23.43,49.4) v1(23.5,40.11) v1(23.62,44.31) v1(23.76,85.57) v1(23.76,83.03) v1(23.83,31.55) v1(23.83,29.4) v1(23.85,27.14) v1(23.82,18.4) v1(23.92,35.02) v1(24.17,80.69) v1(24.21,55.92) v1(24.26,48.89) v1(24.24,47.06) v1(24.21,25.65) v1(24.38,21.55) v1(24.39,37.11) v1(24.52,40.08) v1(24.64,71.95) v1(24.61,44.44) v1(24.73,15.81) v1(24.77,11.17) v1(24.85,35.94) v1(25.03,84.3) v1(25.03,81.76) v1(25.16,54.32) v1(25.15,45.71) v1(25.17,18.91) v1(25.23,60.35) v1(25.22,58.55) v1(25.26,56.33) v1(25.58,22.25) v1(25.72,79.7) v1(25.7,16.52) v1(25.91,12.69) v1(26.09,75.48) v1(26.11,7.95) v1(26.3,85.57) v1(26.3,83.03) v1(26.35,19.58) v1(26.57,56.87) v1(26.54,14.18) v1(26.54,11.17) v1(26.62,60.14) v1(26.6,54.38) v1(26.69,17.39) v1(27.57,84.3) v1(27.57,81.76) v1(27.62,22.22) v1(27.69,73.53) v1(27.69,72.64) v1(27.81,18.12) v1(28.32,11.17) v1(28.29,7.92) v1(28.84,85.57) v1(28.84,83.03) v1(28.84,80.49) v1(28.82,19.01) v1(28.96,73.52) v1(28.96,72.63) v1(29.76,84.3) v1(29.97,12.55) v1(30.11,81.76) v1(30.11,79.22) v1(30.11,76.68) v1(30.52,19.32) v1(30.53,7.9) v1(30.67,20.99) v1(31.24,55.23) v1(31.5,11.17) v1(32.65,81.76) v1(32.77,12.54) v1(32.84,7.94) v1(32.99,58.13) v1(33.15,79.22) v1(33.15,76.68) v1(33.29,55.99) v1(33.46,84.3) v1(33.92,85.57) v1(33.92,83.03) v1(33.92,80.49) v1(33.92,77.95) v1(34,70.35) v1(34.16,11.17) v1(34.73,70.34) v1(34.75,56.32) v1(34.95,7.94) v1(35.19,84.3) v1(35.19,81.76) v1(35.19,79.22) v1(35.19,76.68) v1(35.33,12.53) v1(36.32,55.31) v1(36.5,56.78) v1(36.67,11.26) v1(37.13,7.94) v1(37.57,56.78) v1(37.85,12.54) v1(38.35,55.39) v1(38.71,56.78) v1(39.12,11.17) v1(39.34,7.94) v1(39.67,56.78) v1(39.9,55.39) v1(40.39,12.54) v1(41.12,56.78) v1(41.2,55.46) v1(41.78,60.19) v1(41.78,11.17) v1(41.87,7.9) v1(42.72,55.46) v1(42.93,12.54) v1(43.89,60.24) v1(43.97,55.49) v1(44.13,23.98) v1(44.32,11.17) v1(44.48,56.78) v1(44.42,54.52) v1(45.47,12.54) v1(46.2,53.23) v1(46.46,54.47) v1(46.52,37.77) v1(46.74,11.17) v1(47.1,39.2) v1(47.27,56.78) v1(47.72,35.66) v1(47.79,12.53) v1(47.9,54.55) v1(48,37.94) v1(49.04,36.87) v1(49.15,11.17) v1(49.38,39.21) v1(49.39,53.25) v1(49.68,56.78) v1(50.33,12.54) v1(50.73,38.59) v1(51.28,56.78) v1(51.69,11.17) v1(51.91,53.25) v1(52.87,12.53) v1(53.02,7.93) v1(53.11,29.34) v1(53.19,49.21) v1(53.97,35.41) v1(54.23,11.17) v1(54.43,60.34) v1(54.69,49.04) v1(54.78,33.36) v1(55.27,36.72) v1(55.2,7.93) v1(55.43,51.39) v1(55.39,34.71) v1(55.41,12.53) v1(55.78,69.4) v1(55.97,52.72) v1(56.07,81.51) v1(56.07,76.04) v1(56,73.67) v1(56,71.58) v1(56.37,49.04) v1(56.46,78.71) v1(56.64,11.17) v1(56.99,35.98) v1(57.04,34.05) v1(57.26,85.41) v1(57.41,7.93) v1(57.87,34.98) v1(57.95,12.53) v1(58.42,84.7) v1(58.94,67.83) v1(59.82,11.17) v1(59.83,7.93) v1(60.11,85.1) v1(61.22,67.83) v1(61.62,13.96) v1(61.88,85.13) v1(61.83,12.88) v1(61.94,7.93) v1(63.15,14.22) v1(63.37,15.73) v1(63.39,67.78) v1(64.12,7.93) v1(64.38,85.12) v1(64.84,15.9) v1(65.03,17.37) v1(65.31,14.8) v1(66.33,17.38) v1(66.33,7.93) v1(66.77,15.89) v1(66.88,79.36) v1(66.8,66.16) v1(68.33,80.51) v1(68.94,15.47) v1(69.15,18.24) v1(69.39,75.05) v1(69.48,66.47) v1(69.73,20.39) v1(70.28,16.81) v1(70.41,78.35) v1(70.63,18.22) v1(70.71,69.81) v1(70.82,75.71) v1(71.17,79.78) v1(71.12,73.27) v1(71.52,15.45) v1(71.61,21.95) v1(71.6,20.07) v1(71.84,85.92) v1(72.06,74.56) v1(72.14,72.63) v1(72.19,70.4) v1(72.21,16.68) v1(72.8,78.37) v1(73,22.55) v1(73.07,20.16) v1(73.12,84.24) v1(73.17,18.07) v1(73.09,14) v1(73.58,62.13) v1(73.74,79.77) v1(74.01,14.93) v1(74.1,19.06) v1(74.3,86.03) v1(74.84,13.53) v1(75.15,78.37) v1(75.13,19.89) v1(75.14,18.02) v1(75.15,16.05) v1(75.18,76.82) v1(75.46,63.67) v1(75.56,69.36) v1(75.76,84.29) v1(75.94,15.24) v1(76.17,79.78) v1(76.2,26.15) v1(76.38,12.77) v1(76.47,18.56) v1(76.4,16.75) v1(76.5,20.02) v1(76.68,14.51) v1(76.74,86.03) v1(76.83,70.3) v1(77.24,73.42) v1(77.22,38.22) v1(77.57,20.39) v1(77.6,81.14) v1(77.66,19.06) v1(77.63,17.41) v1(77.67,15.48) v1(77.72,69.34) v1(77.95,82.01) v1(77.89,14.15) v1(77.98,12.77) v1(78.16,70.96) v1(78.28,75.74) v1(78.28,79.34) v1(78.31,77.33) v1(78.33,73.79) v1(78.9,86.02) v1(79.05,62.28) v1(79.02,41.06) v1(79.09,59.55) v1(79.25,84.06) v1(79.38,36.55) v1(79.71,77.97) v1(79.76,75.94) v1(79.88,74.58) v1(79.9,60.74) v1(80.26,63.62) v1(80.31,58.61) v1(80.52,77.1) v1(80.58,24.38) v1(80.86,84.35) v1(80.81,78.81) v1(80.98,62.28) v1(81.01,74.54) v1(81.18,41.03) v1(81.48,35.86) v1(81.53,59.55) v1(81.57,58.53) v1(81.51,43.26) v1(81.57,24.4) v1(81.53,22.09) v1(81.53,21.2) v1(81.53,20.31) v1(81.53,19.42) v1(81.56,14.16) v1(81.63,86.07) v1(81.66,63.62) v1(81.74,30.16) v1(81.74,28.39) v1(81.72,26.78) v1(81.79,16.85) v1(82.07,75.58) v1(82.12,83) v1(82.33,77.28) v1(82.3,73.24) v1(82.33,60.74) v1(82.35,15.48) v1(82.43,57.39) v1(82.52,24.39) v1(82.58,12.77) v1(82.84,29.29) v1(82.85,27.68) v1(82.94,84.35) v1(82.95,58.59) v1(82.92,33.59) v1(83.19,74.44) v1(83.32,35.85) v1(83.43,76.17) v1(83.44,64.25) v1(83.41,63.08) v1(83.62,41.03) v1(83.69,32.34) v1(83.84,61.83) v1(83.88,30.16) v1(83.8,14.15) v1(83.97,67.95) v1(83.94,59.55) v1(83.9,28.44) v1(84.07,73.57) v1(84.07,71.64) v1(84.14,50.34) v1(84.23,86.03) v1(84.24,78.86) v1(84.21,43.25) v1(84.33,16.85) v1(84.75,60.74) v1(84.72,37.69) v1(84.72,36.04) v1(84.71,31.18) v1(84.81,40.12) v1(84.79,33.49) v1(84.84,12.77) v1(85.01,82.95) v1(85.09,84.35) v1(85.13,57.66) v1(85.09,56.51) v1(85.13,15.46) v1(85.22,66.94) v1(85.22,64.25) v1(85.32,63.19) v1(85.45,77.69) v1(85.62,68.93) v1(85.68,32.34) v1(85.59,29.97) v1(85.59,27.17) v1(85.6,25.9) v1(85.6,23.99) v1(85.92,58.6) v1(86.15,41.56) v1(86.21,74.46) v1(86.23,73.12) v1(86.26,71.69) v1(86.35,61.76) v1(86.36,14.16) v1(86.41,86.03) v1(86.41,38.78) v1(86.66,82.95) v1(86.61,59.55) v1(86.59,37.14) v1(86.87,16.85) v1(87,84.35) v1(86.99,64.25) v1(87.11,69.32) v1(87.11,66.78) v1(87.17,63.19) v1(87.41,60.74) v1(87.87,57.66) v1(87.9,71.53) v1(87.92,43.97) v1(87.92,42.95) v1(87.88,37.2) v1(87.96,29.74) v1(87.98,26.96) v1(87.96,22.3) v1(87.93,12.77) v1(88.07,39.65) v1(87.99,34.69) v1(88,32.66) v1(87.99,24.98) v1(88.04,15.48) v1(88.24,73.12) v1(88.39,82.92) v1(88.38,17.09) v1(88.54,86.03) v1(88.8,58.59) v1(89.03,41.65) v1(89.03,14.16) v1(89.11,54.44) v1(89.23,43.24) v1(89.31,61.76) v1(89.43,16.91) v1(89.51,75.86) v1(89.59,71.49) v1(89.72,63.33) v1(89.71,59.58) v1(89.78,28.4) v1(89.79,36.68) v1(89.79,34.31) v1(89.78,31.26) v1(89.78,25.82) v1(89.78,23.14) v1(89.79,20.95) v1(89.98,74.46) v1(90.05,66.09) v1(90.04,55.47) v1(90.1,84.63) v1(90.27,79.02) v1(90.32,73.09) v1(90.3,15.48) v1(90.4,86.05) v1(90.51,42.27) v1(90.55,12.77) v1(90.71,63.46) v1(90.77,43.97) v1(90.71,18.11) v1(90.8,60.67) v1(91.03,75.85) v1(91.01,54.31) v1(91.03,40.51) v1(91.17,77.68) v1(91.19,56.54) v1(91.44,16.86) v1(91.56,71.49) v1(91.57,36.04) v1(91.52,33.81) v1(91.55,31.52) v1(91.58,14.16) v1(91.67,39.22) v1(91.72,63.19) v1(91.87,61.76) v1(91.8,41.55) v1(92.03,74.48) v1(92.02,73.09) v1(92.17,57.66) v1(92.19,54.3) v1(92.45,55.56) v1(92.75,76.23) v1(92.75,18.11) v1(92.75,15.49) v1(92.97,65.78) v1(93.04,12.77) v1(93.14,74.47) v1(93.24,73.12) v1(93.45,77.68) v1(93.55,58.59) v1(93.84,54.19) v1(93.98,86.1) v1(93.98,16.86) v1(94.11,80.25) v1(94.12,14.16) v1(94.26,71.14) v1(94.35,84.02) v1(94.49,59.55) v1(94.54,48.45) v1(94.77,65.72) v1(94.89,67.96) v1(94.92,53.5) v1(95,81.78) v1(95.01,71.67) v1(95.14,57.67) v1(95.22,74.46) v1(95.29,18.11) v1(95.29,15.49) v1(95.48,86.05) v1(95.56,58.6) v1(95.58,12.77) v1(95.66,63.41) v1(95.71,80.28) v1(95.81,73.12) v1(95.9,70.78) v1(95.95,68.94) v1(95.88,60.7) v1(95.99,67.12) v1(96.27,53.46) v1(96.48,64.44) v1(96.52,16.86) v1(96.67,44.91) v1(96.66,14.16) v1(96.77,81.78) v1(96.77,71.63) v1(96.82,69.85) v1(96.84,66.06) v1(96.83,59.54) v1(96.85,54.92) v1(96.9,76.21) v1(97.11,68) v1(97.42,63.4) v1(97.41,48.38) v1(97.51,74.49) v1(97.64,57.63) v1(97.83,18.11) v1(97.83,15.49) v1(97.9,77.59) v1(97.97,58.59) v1(98.02,86.05) v1(98.04,83.68) v1(97.99,80.28) v1(98.07,71.59) v1(98.04,60.7) v1(98.1,54.91) v1(98.15,12.77) v1(98.25,44.91) v1(98.42,82.41) v1(98.68,64.51) v1(98.7,65.58) v1(98.87,54.27) v1(98.93,76.21) v1(98.9,53.15) v1(98.9,51.94) v1(98.89,18.31) v1(99.03,59.55) v1(99.18,74.49) v1(99.16,73.12) v1(99.15,16.87) v1(99.24,49.49) v1(99.25,14.15) v1(99.47,54.92) v1(99.76,63.4) v1(99.95,81.78) v1(99.93,77.59) v1(100.12,58.6) v1(100.2,83.68) v1(100.27,65.59) v1(100.24,60.69) v1(100.31,64.39) v1(100.38,15.48) v1(100.56,86.05) v1(100.54,74.47) v1(100.54,19.02) v1(100.58,73.12) v1(100.79,71.7) v1(101.08,78.97) v1(101.01,59.57) v1(101.5,12.77) v1(101.73,56.46) v1(102.03,55.5) v1(102.07,54.48) v1(102.21,60.68) v1(102.27,17.02) v1(102.36,83.68) v1(102.31,15.15) v1(102.56,21.06) v1(102.62,49.39) v1(102.62,46.98) v1(102.74,73.12) v1(102.86,58.6) v1(102.91,19.55) v1(103.1,86.05) v1(103.25,67.55) v1(103.35,54.51) v1(103.38,59.55) v1(103.76,64.76) v1(103.76,63.87) v1(103.76,22.17) v1(103.74,20.39) v1(103.84,57.67) v1(103.94,55.75) v1(104.16,15.07) v1(104.27,67.55) v1(104.27,66.66) v1(104.27,65.65) v1(104.21,18.96) v1(104.28,17.11) v1(104.3,54.5) v1(104.33,23.65) v1(104.56,60.22) v1(104.66,21.3) v1(104.71,78.92) v1(104.69,76.5) v1(104.7,69.41) v1(104.9,83.68) v1(104.95,56.54) v1(105.03,58.59) v1(105.03,22.97) v1(105.09,54.48) v1(105.23,75.48) v1(105.41,35.68) v1(105.44,32.8) v1(105.44,30.26) v1(105.44,28.03) v1(105.55,85.25) v1(105.54,74.13) v1(105.54,49.39) v1(105.54,46.98) v1(105.66,24.93) v1(105.75,71.67) v1(105.84,77.74) v1(105.81,20.56) v1(105.92,63.95) v1(106.02,82.13) v1(105.99,72.58) v1(106.08,69.26) v1(106.17,70.98) v1(106.12,67.3) v1(106.17,65.32) v1(106.17,17.1) v1(106.35,56.49) v1(106.45,57.68) v1(106.81,75.57) v1(106.81,21.6) v1(106.98,76.5) v1(106.88,23.53) v1(107,78.92) v1(107.06,74.13) v1(107.21,37.71) v1(107.35,55.65) v1(107.29,47.92) v1(107.41,81.94) v1(107.44,68.57) v1(107.44,67.3) v1(107.47,25.41) v1(107.68,63.01) v1(107.7,83.68) v1(107.76,58.05) v1(107.73,35.53) v1(107.74,32.34) v1(107.79,29.29) v1(107.83,27.27) v1(107.88,20.73) v1(108.05,70.07) v1(107.98,18.92) v1(108.14,85.27) v1(108.13,77.74) v1(108.26,24.9) v1(108.2,22.98) v1(108.38,47.92) v1(108.52,75.49) v1(108.71,74.13) v1(108.71,72.63) v1(108.76,36.14) v1(108.77,34.03) v1(108.76,30.67) v1(108.76,27.48) v1(108.93,80.41) v1(109.07,69.03) v1(109.04,61.1) v1(109.3,56.63) v1(109.47,82.29) v1(109.47,46.75) v1(109.78,20.71) v1(109.83,24.58) v1(109.96,70.14) v1(110.06,26.98) v1(110.14,32.11) v1(110.14,29.18) v1(110.2,36.13) v1(110.25,33.88) v1(110.36,75.43) v1(110.3,38) v1(110.49,74.13) v1(110.49,72.63) v1(110.69,85.23) v1(111.25,80.51) v1(111.29,84.38) v1(111.58,22.51) v1(111.76,75.68) v1(111.79,72.63) v1(111.84,33.54) v1(111.84,31.36) v1(111.84,27.11) v1(111.89,36.13) v1(111.94,29.23) v1(112.07,53.24) v1(112.78,40.83) v1(113.03,66.54) v1(113.17,39.25) v1(113.37,24.3) v1(113.47,81.11) v1(113.47,78.6) v1(113.48,36.1) v1(113.42,31.36) v1(113.41,29.25) v1(113.46,26.91) v1(113.54,75.68) v1(113.49,73.98) v1(113.5,33.61) v1(114.02,42.18) v1(114.02,38.19) v1(114.17,71.36) v1(114.71,72.79) v1(114.86,74.49) v1(114.94,79.36) v1(114.94,76.82) v1(114.88,53) v1(115.11,41.24) v1(115.09,33.57) v1(115.2,36.12) v1(115.29,61.56) v1(115.32,30.94) v1(115.35,26.37) v1(115.42,69.73) v1(115.44,28.24) v1(115.54,71.95) v1(115.7,39.84) v1(115.8,86.05) v1(115.8,83.51) v1(115.82,46.29) v1(115.82,37.99) v1(116.07,75.47) v1(116.38,71.11) v1(116.48,72.89) v1(116.6,68.98) v1(116.76,64.97) v1(116.76,62.53) v1(116.71,53.02) v1(116.76,51.35) v1(116.78,45.07) v1(116.93,13.01) v1(117.07,84.78) v1(117.04,74.41) v1(117.25,72.1) v1(117.68,8.91) v1(117.71,67.69) v1(117.73,43.88) v1(118.06,65.85) v1(118.08,63.8) v1(118.08,61.39) v1(118.08,69.41) v1(118.25,52.73) v1(118.26,49.57) v1(118.34,86.05) v1(118.34,83.51) v1(118.37,58.84) v1(118.36,56.07) v1(118.52,74.38) v1(118.49,70.88) v1(118.74,42.89) v1(118.78,12.94) v1(119,72.43) v1(119.08,39.39) v1(119.61,84.76) v1(119.75,61.77) v1(119.76,58.51) v1(119.74,55.33) v1(119.72,53.82) v1(119.74,48.22) v1(119.81,67.33) v1(119.79,65.15) v1(119.97,17.81) v1(120.02,69.36) v1(120.73,70.68) v1(120.88,86.03) v1(120.88,83.49) v1(121.05,75.05) v1(121.03,72.98) v1(121.09,77.54) v1(121.18,66.94) v1(121.19,62.95) v1(121.19,60.39) v1(121.21,56.73) v1(121.18,54.14) v1(121.19,52) v1(121.18,47.23) v1(121.32,17.79) v1(121.41,19.63) v1(121.64,84.76) v1(122.28,69.13) v1(122.56,64.24) v1(122.56,61.7) v1(122.56,59.16) v1(122.56,56.62) v1(122.56,54.08) v1(122.56,46.46) v1(122.56,43.92) v1(122.56,41.38) v1(122.56,38.84) v1(122.56,36.3) v1(122.56,33.76) v1(122.56,31.22) v1(122.56,28.68) v1(122.56,26.14) v1(122.56,23.6) v1(122.56,21.06) v1(122.56,18.52) v1(122.56,17) v1(122.66,85.82) v1(122.63,48.9) v1(122.68,67.3) v1(122.71,51.79) v1(122.85,76.2) v1(122.83,74.04) v1(122.83,71.6) v1(122.91,84.76) v1(122.91,83.49) v1(122.91,78.57) v2(16.89,59.93) v2(16.89,58.28) v2(19.81,73) v2(19.92,69.45) v2(19.94,67.68) v2(19.99,71.18) v2(21.33,70.22) v2(21.4,75.42) v2(21.43,68.43) v2(21.46,65.14) v2(22.58,63.43) v2(22.64,65.95) v2(22.61,39.85) v2(22.94,69.96) v2(23.04,67.97) v2(23.12,75.44) v2(23.6,51.69) v2(23.76,41.12) v2(24.43,64.05) v2(24.57,70.08) v2(24.61,75.68) v2(24.64,41.25) v2(24.84,65.93) v2(24.92,50.9) v2(24.9,42.14) v2(25.13,30.58) v2(25.13,26.54) v2(25.29,67.74) v2(25.43,38.1) v2(25.56,50.19) v2(25.67,51.72) v2(25.69,34.72) v2(25.83,24.02) v2(25.88,36.85) v2(26,71.01) v2(26.08,69.27) v2(26.04,48.83) v2(26.11,72.33) v2(26.24,74) v2(26.37,45.59) v2(26.3,41.86) v2(26.62,27.75) v2(26.88,66.22) v2(26.83,26.72) v2(26.98,68.3) v2(27,51.81) v2(27.03,48.82) v2(27.21,63.65) v2(27.52,64.83) v2(27.57,27.99) v2(27.59,24.08) v2(27.75,70.33) v2(28.12,51.81) v2(28.18,35.03) v2(28.26,67.19) v2(28.4,26.34) v2(28.4,25.09) v2(28.76,45.59) v2(28.81,49.25) v2(28.8,28.65) v2(28.96,71.74) v2(29.04,47.68) v2(29.17,63.63) v2(29.17,30.81) v2(29.21,54.43) v2(29.46,65.98) v2(29.48,51.75) v2(29.79,67.17) v2(29.88,26.72) v2(29.95,46.8) v2(30.07,48.69) v2(30.03,29.74) v2(30.13,24.59) v2(30.13,23.34) v2(30.21,50.63) v2(30.84,51.28) v2(30.94,64.84) v2(30.98,47.82) v2(31.12,49.74) v2(31.27,25.3) v2(31.27,22.99) v2(31.57,63.46) v2(31.65,65.99) v2(31.76,50.39) v2(31.91,31.83) v2(32.02,48.84) v2(32.74,63.9) v2(32.79,32.7) v2(32.9,67.05) v2(32.89,60.37) v2(33.31,64.98) v2(33.41,33.32) v2(34.04,61) v2(34.25,34.16) v2(34.49,65.47) v2(34.87,61.76) v2(35.13,35.05) v2(35.2,58.08) v2(35.38,59.65) v2(35.79,62.53) v2(36,35.92) v2(36.37,60.29) v2(36.42,63.53) v2(36.56,27.43) v2(36.56,26.26) v2(36.87,36.79) v2(36.86,24.94) v2(36.86,23.72) v2(36.98,61.33) v2(37.16,57.93) v2(37.68,62.44) v2(37.67,59.07) v2(37.74,41.12) v2(37.74,37.65) v2(37.9,42.58) v2(37.9,27.43) v2(38.46,24.94) v2(38.51,61.53) v2(38.61,38.53) v2(38.71,60.21) v2(38.71,59.04) v2(38.71,57.93) v2(38.87,23.72) v2(39.48,39.39) v2(39.62,60.21) v2(39.67,59.04) v2(39.75,57.93) v2(39.84,61.62) v2(40.77,35.32) v2(41.13,61.63) v2(41.15,40.88) v2(41.68,57.93) v2(41.73,59.04) v2(41.89,46.29) v2(42.21,46.95) v2(42.85,56.78) v2(42.96,23.52) v2(43.01,47.83) v2(43.18,50.79) v2(43.19,49.83) v2(43.31,54.09) v2(43.31,33.39) v2(43.59,46.86) v2(43.62,46.05) v2(43.87,59.04) v2(44.01,61.58) v2(44.22,53.23) v2(44.27,45.55) v2(44.3,57.93) v2(44.43,49.8) v2(44.62,31.43) v2(45.32,23.52) v2(45.81,61.55) v2(46.1,60.19) v2(46.1,59.04) v2(46.41,55.31) v2(46.61,28.67) v2(47.24,57.93) v2(47.34,61.56) v2(47.33,29.11) v2(47.55,55.34) v2(48.23,60.21) v2(48.23,59.04) v2(48.26,24.88) v2(48.76,45.45) v2(49.25,54.4) v2(49.56,57.93) v2(49.96,60.24) v2(50.01,55.54) v2(50.29,61.56) v2(50.29,24.45) v2(50.55,59.04) v2(50.55,28.37) v2(51.38,60.65) v2(51.36,55.54) v2(51.44,54.4) v2(51.49,57.93) v2(51.77,62.78) v2(52.04,61.33) v2(52.16,59.78) v2(52.38,40.11) v2(52.3,24.78) v2(52.79,57.01) v2(52.83,55.57) v2(52.94,64.15) v2(52.96,60.59) v2(53.09,59.02) v2(53.26,62.55) v2(53.19,42.64) v2(53.72,59.65) v2(53.85,58.08) v2(53.97,54.73) v2(54.13,61.76) v2(54.56,58.79) v2(54.66,57.11) v2(54.74,53.71) v2(54.74,44.17) v2(55.11,27.65) v2(55.32,64.89) v2(55.36,31.62) v2(55.45,54.4) v2(55.58,56.38) v2(55.65,58.11) v2(55.75,61.33) v2(55.8,60.04) v2(55.85,46.65) v2(56.06,63.67) v2(56.03,62.47) v2(56.13,85.97) v2(56.45,56.85) v2(56.72,55.44) v2(57.08,29.62) v2(57.15,58.92) v2(57.66,52.57) v2(57.95,61.33) v2(58.02,37.03) v2(58.17,64.94) v2(58.37,60.19) v2(58.47,63.67) v2(58.39,62.47) v2(58.39,30.92) v2(58.78,55.44) v2(58.82,39.44) v2(59.31,76.57) v2(59.44,73.27) v2(59.44,58.92) v2(59.74,60.19) v2(59.78,56.39) v2(60.12,64.86) v2(60.25,61.32) v2(60.42,45.84) v2(60.73,63.64) v2(60.69,31.32) v2(60.88,62.47) v2(61.01,60.19) v2(61.02,56.24) v2(61.22,48.23) v2(61.22,47.43) v2(61.22,44.24) v2(61.22,42.63) v2(61.22,39.43) v2(61.47,70.09) v2(61.84,50.4) v2(61.9,61.31) v2(61.9,58.44) v2(61.94,49.63) v2(62.36,81.78) v2(62.36,79.75) v2(62.31,57.77) v2(62.34,56.1) v2(62.38,64.89) v2(62.43,59.73) v2(62.89,63.67) v2(63.11,62.36) v2(63.27,60.59) v2(63.53,48.31) v2(63.63,70.09) v2(63.68,56.39) v2(63.62,41.03) v2(63.74,46.76) v2(63.8,64.86) v2(63.93,58.08) v2(63.93,50.28) v2(64.01,73.27) v2(64.03,63.19) v2(63.99,59.85) v2(64.14,76.57) v2(64.17,61.32) v2(64.14,47.5) v2(64.14,45.16) v2(64.32,46.76) v2(64.42,50.63) v2(64.55,43.9) v2(64.87,64.12) v2(64.85,54.05) v2(64.97,62.17) v2(64.95,56.39) v2(65.22,41.03) v2(65.41,81.78) v2(65.61,58.23) v2(65.68,59.78) v2(65.86,63.13) v2(65.91,80.38) v2(66.01,44.11) v2(66.14,61.03) v2(66.67,69.97) v2(66.73,62.25) v2(66.87,73.14) v2(66.81,71.81) v2(66.87,56.97) v2(66.82,48.24) v2(66.78,43.54) v2(66.89,77.07) v2(67.11,75.12) v2(67.72,59.45) v2(67.79,57.67) v2(67.94,64.89) v2(68.07,60.95) v2(68.19,77.2) v2(68.3,55.54) v2(68.44,78.54) v2(68.94,58.26) v2(69.26,79.4) v2(69.22,59.76) v2(69.34,56.1) v2(69.72,62.98) v2(70.08,81.17) v2(70.08,57.01) v2(70.48,58.54) v2(71.38,43.19) v2(71.55,61.1) v2(71.62,32.98) v2(71.61,30.78) v2(71.61,26.97) v2(72.39,81.15) v2(73.05,25.19) v2(73.13,35.27) v2(73.1,33.7) v2(73.1,31.41) v2(73.12,28.31) v2(73.23,59.4) v2(73.34,38.49) v2(73.75,57.48) v2(74.17,55.62) v2(74.19,41.19) v2(74.37,35.06) v2(74.35,27.53) v2(74.37,25.79) v2(74.37,22.03) v2(74.41,31.93) v2(74.41,29.76) v2(74.4,24.09) v2(74.65,59.96) v2(74.65,57.93) v2(75.28,81.19) v2(75.67,57.83) v2(75.68,55.66) v2(75.84,59.98) v2(75.88,49.76) v2(75.98,40.03) v2(76.53,74.26) v2(76.55,62.4) v2(76.56,50.62) v2(76.83,61) v2(76.81,39.44) v2(77.27,59.63) v2(77.32,41.01) v2(77.84,63.6) v2(77.98,60.34) v2(77.98,26.15) v2(78.26,37.56) v2(78.33,39.97) v2(78.64,43.25) v2(79.2,49.69) v2(81.58,53.4) v2(82.75,50.49) v2(82.79,30.7) v2(82.98,53.48) v2(83.08,54.65) v2(84.44,54.39) v2(85.14,50.41) v2(86.64,56.44) v2(92.6,26.76) v2(93.13,41.5) v2(93.14,39.17) v2(93.34,28.44) v2(93.6,26.79) v2(94.49,26.79) v2(94.83,29.63) v2(95.38,37.84) v2(95.8,28.39) v2(96.2,41.94) v2(96.65,38.47) v2(96.9,29.96) v2(97.14,33.83) v2(97.9,34.57) v2(97.89,33.02) v2(99.66,34.03) v2(100.2,57.39) v2(101.6,30.09) v2(102.02,28.46) v2(102.23,33.77) v2(102.53,35.74) v2(102.6,36.75) v2(102.74,31.74) v2(102.77,30.88) v2(103.36,25.94) v2(104.72,42.51)
